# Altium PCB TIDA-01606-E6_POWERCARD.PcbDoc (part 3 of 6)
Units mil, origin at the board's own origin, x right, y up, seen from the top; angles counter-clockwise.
Board outline 13779.53 x 7874.02 mil, 4 copper layers (Top Layer, Gnd Layer, Pwr Layer, Bottom Layer), stack 94.4 mil thick; 550 components, 292 nets, 1594 pads, 572 vias.
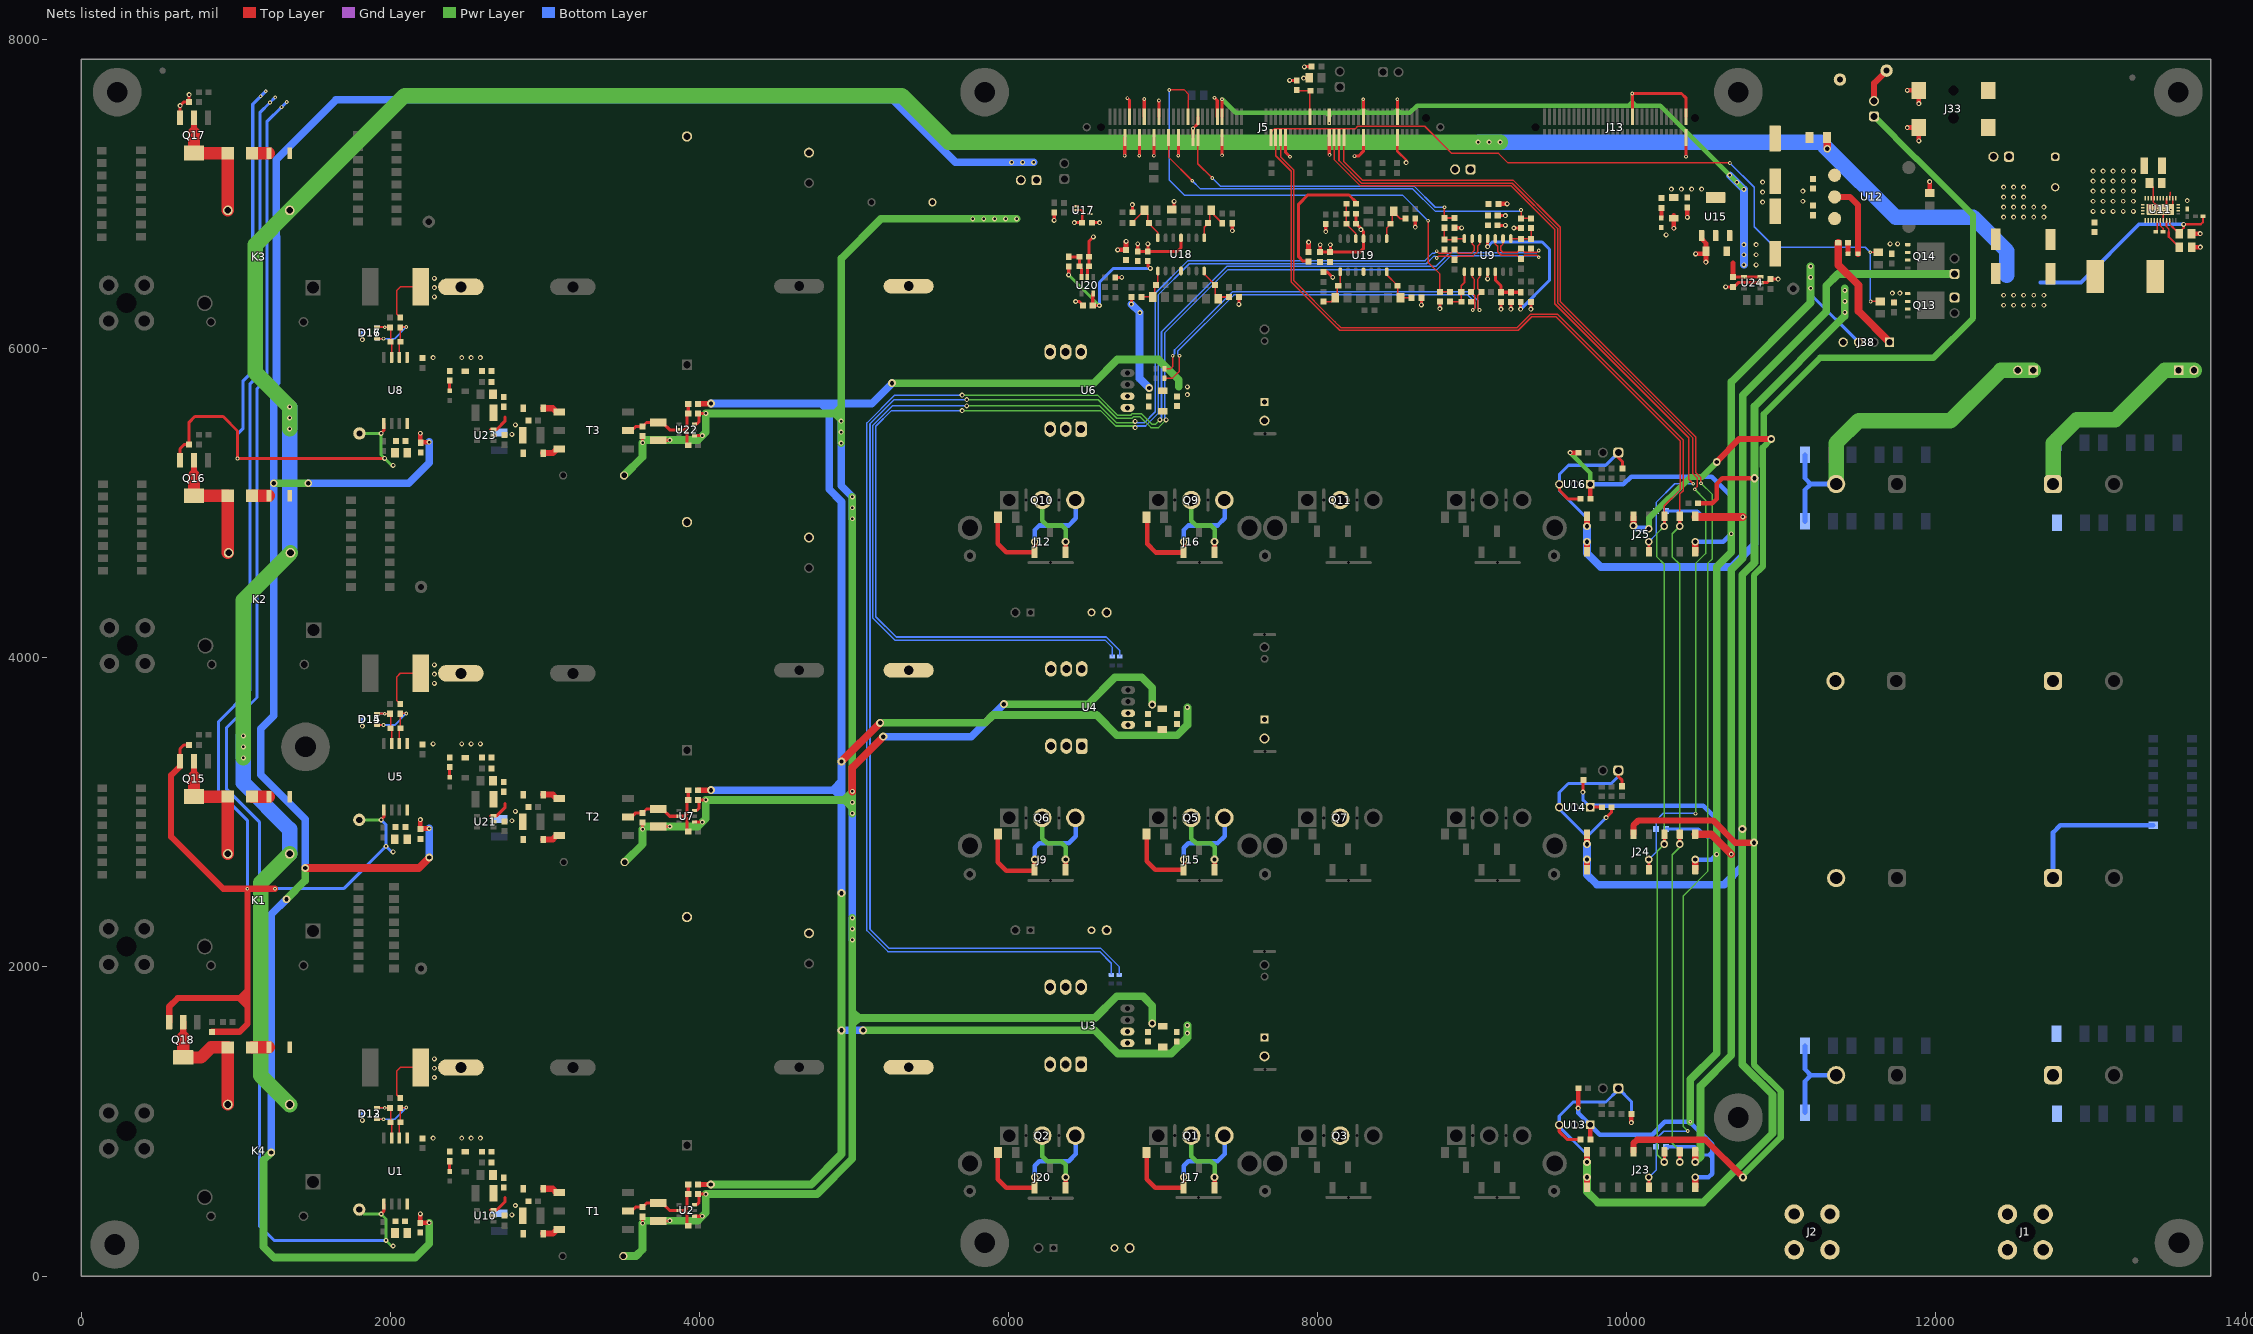
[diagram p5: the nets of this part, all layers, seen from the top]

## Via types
v1: diameter 32, hole 16, Top Layer to Bottom Layer, 336 vias
v2: diameter 24, hole 12, Top Layer to Bottom Layer, 140 vias
v3: diameter 50, hole 28, Top Layer to Bottom Layer, tented both sides, 65 vias
v4: diameter 52, hole 28, Top Layer to Bottom Layer, 14 vias
v5: diameter 19.68, hole 7.87, Top Layer to Bottom Layer, 10 vias
v6: diameter 50, hole 28, Top Layer to Bottom Layer, 7 vias

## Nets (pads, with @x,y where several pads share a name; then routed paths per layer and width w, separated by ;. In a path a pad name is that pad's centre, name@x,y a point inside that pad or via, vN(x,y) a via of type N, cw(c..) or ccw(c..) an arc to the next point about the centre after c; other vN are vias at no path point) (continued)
3.3V: C44.1 C49.1 C53.2 C90.2 C91.2 C92.2 J23.16 J24.16 J25.16 J38.3 L7.1 L8.1 L13.1 L17.1 L21.1 L23.1 R8.2 R11.2 R32.2 R35.2 R55.2 R64.2 R91.2 R208.2 U13.1 U14.1 U15.2 U15.4 U16.1 U17.1 U17.4 U17.5 | length 29376.6
  Top Layer w15: C53.2@6528.29,6826.56 C53.2@6539.3,6815.55
  Top Layer w20: C53.2@6539.3,6815.55 v1(6589.8,6815.55) ; v1@6760.41,6694 v1(6760.87,6694.46) ; v1(7909,7750) 7912,7753 R35.2@7945.33,7753 R35.2@7951.87,7753 ; v1@7941,6689 v1(7941.46,6689.46) ; v1(9716,3131) 9716,3204.5 R64.2@9720,3208.5 ; U14.1@9763.54,3034 C91.2@9839.5,3034
  Top Layer w30: v1(2195,402.98) 2195,346 v1(2251.98,346) ; v1(2195,2952.98) 2195,2896 v1(2251.98,2896) ; v1(2195,5452.98) 2195,5396 v1(2251.98,5396) ; v1(6705.87,6639.46) 6760.41,6639.46 v1@6760.41,6694 ; L23.1@7941,6634.46 v1@7941,6689 ; L17.1@9169.5,6937 v1(9226,6937) ; v1(9633.33,5327.33) R91.2@9687.01,5327.33 ; v1(9686,1087) 9687.01,1088.01 R55.2@9687.01,1215.2 ; U13.1@9763.54,977.94 9764.5,976.98 C90.2@9764.5,884 ; U16.1@9764.61,5122.01 9764.6,5029.39 C92.2@9764.99,5029
  Top Layer w40: J23.16@10442.93,574.56 v3(10442.93,638.93) ; J24.16@10442.93,2630.62 v3(10442.93,2694.99) ; J25.16@10442.93,4686.69 v3(10442.93,4751.06)
  Top Layer w50: v6(1450,2640) 2184,2640 v6(2251.98,2707.98)
  Pwr Layer w30: v1(9633.33,5327.33) 9764.6,5196.06 U16.1@9764.61,5122.01
  Pwr Layer w50: v6(1230,800) 1180,750 1180,190 1250,120 2162.14,120 2251.98,209.85 v1(2251.98,346) ; v6(1247,5130) v6(1470,5130) ; v6(1329,2439) 1450,2560 v6(1450,2640) ; v2(10411,999) 10411,1272 10582,1443 10582,2708 v1(10582,2729) 10582,4589 10676,4683 v1(10676,4803) 10676,5784 11189,6297 v1(11189,6391) v1(11189,6462) v1(11189,6533)
  Bottom Layer w20: v1(9716,3131) 9716,3081.54 U14.1@9763.54,3034 ; R32.2@10252.79,837.06 10441.94,837.06 10494,785 10530,785 ; R8.2@10252.79,2893.12 10464.88,2893.12 10516,2842 10582,2842 ; R11.2@10252.79,4949.18 10458.94,4949.18 10503.13,4905 10676,4905 ; 10552,763 10530,785 ; 10552,785 10530,785 ; 10552,807 10530,785 ; v1(11189,6391) 11189,6353.17 J38.3@11500,6042.18
  Bottom Layer w30: v1(9686,1087) 9686,1055.47 9826.47,915 10163.87,915 10246.87,998 10406,998 10552,852 10552,807 10552,785 10552,763 10552,662 10528.93,638.93 v3(10442.93,638.93) ; U14.1@9763.54,3034 9772.53,3043 10495,3043 10582,2956 10582,2842 v1(10582,2729) 10547.99,2694.99 v3(10442.93,2694.99) ; U16.1@9764.61,5122.01 9978.01,5122.01 10028,5172 10549,5172 10676,5045 10676,4905 v1(10676,4803) 10624.05,4751.06 v3(10442.93,4751.06)
  Bottom Layer w50: v6(1230,800) 1230,2340 v6(1329,2439) ; v6(1450,2640) 1450,2955 1162,3243 1162,3541.4 1247,3626.4 v6(1247,5130) 1247,5763.31 1264.37,5780.68 1264.37,6725.17 1263,6726.55 1263,7223 1650,7610 5253,7610 5657,7206 v1(6021,7206) v1(6092,7206) v1(6163,7206) ; v6(1470,5130) 2120,5130 2251.98,5261.98 v1(2251.98,5396) ; v6(2251.98,2707.98) v1(2251.98,2896)
  other v1: 10289,7032 10354,7032 10419,7032 10484,7032
3.3V_U9: C36.2 C37.1 L17.2 R128.1 U9.4 | length 994.8
  Top Layer w20: U9.4@9099.7,6712.46 9099.7,6660.3 v1(9100,6660) ; v1(9313.24,6256.25) 9313.74,6256.75 R128.1@9313.74,6302.25
  Bottom Layer w20: v1(9100,6660) 9130,6690 9453,6690 9500,6643 9500,6443.01 v1(9313.24,6256.25)
3.3V_U18: C47.2 C56.1 C135.2 L21.2 R142.1 U18.4 U20.5 | length 1025.8
  Top Layer w20: v1@6390,6477.67 R142.1@6390,6532.01 ; U20.5@6547.4,6355.87 6545.5,6353.96 C135.2@6545.5,6280 v1@6589,6280 ; C56.1@6901.54,6566.68 6901.54,6536.46 v1(6918,6520)
  Pwr Layer w20: v1(6389.5,6477.18) 6587.18,6279.5 v1(6588.5,6279.5)
  Bottom Layer w20: v1(6588.5,6279.5) 6588.5,6429.37 6679.13,6520 v1(6918,6520)
3.3V_U19: C57.2 C58.1 L23.2 R139.1 U19.4 | length 841.5
  Top Layer w20: L23.2@7941,6567.54 7903.46,6567.54 7877,6594 7877,6935 7936,6994 8203,6994 8249.2,6947.8 R139.1@8249.2,6938
5V: C43.1 C62.1 C66.1 C117.2 J5.48 J5.84 J5.98 J5.112 J13.158 J13.180 J38.1 L9.1 L10.1 L14.1 R53.2 R63.2 R159.2 R207.2 U12.3 U15.3 U24.3 U24.4 | length 22284.4
  Top Layer w20: v2(7382,7614) 7382.4,7613.6 J5.48@7382.4,7500.07 ; v2(8075.31,7460) J5.84@8075.31,7500.07 ; v2(8295.39,7614) 8295.78,7613.6 J5.98@8295.78,7500.07 ; v2(8515.86,7614) 8516.26,7613.6 J5.112@8516.26,7500.07 ; v2(10035.54,7651.34) 10354.66,7651.34 10382.4,7623.6 J13.180@10382.4,7500.07 ; J13.158@10035.94,7500.07 v2@10035.94,7650.94 ; C117.2@10687.61,6463.54 10688.51,6464.44 U24.3@10865.74,6464.44
  Top Layer w30: R53.2@3990.5,592 R53.2@3991.5,593 ; R63.2@3991.5,3143 R63.2@3992.5,3144 ; R159.2@3991.5,5643 R159.2@3993.5,5645 ; C117.2@10687.61,6463.54 10687.61,6554.61
  Top Layer w35: R53.2@3991.5,593 v4(4074,593) ; R63.2@3992.5,3144 v4(4075,3144) ; R159.2@3993.5,5645 v4(4076,5645)
  Top Layer w50: v4(4920,3330) v4(5170,3580) ; R207.2@11368.5,6685 11368.5,6541.5 11500,6410 11500,6242.18 J38.1@11700,6042.18
  Pwr Layer w20: 8045.09,7531 8050.09,7526 8075,7501.09 ; 8073,7526 8074.91,7527.91 ; 8075,7529.09 8075,7526 8075,7501.09 ; v2(8075.31,7460) 8075.31,7500.78 8075,7501.09 ; 8104.83,7526 8107,7526 ; 8104.91,7531 8099.91,7526 8075,7501.09 ; 8273,7526 8273,7531.61 8295.39,7554 ; v2(8295.39,7614) 8295.39,7554 ; 8295.78,7526 8295.39,7526.4 8295.39,7554 ; 8335,7526 8323.39,7526 8295.39,7554 ; 8488,7526 8515.86,7553.86 ; 8515,7526 8515.86,7526.86 8515.86,7553.86 ; v2(8515.86,7614) 8515.86,7553.86 ; 8550,7526 8543.72,7526 8515.86,7553.86 ; 10007.68,7574.14 10035.54,7602 ; 10035.54,7573.4 10035.54,7602 ; v2(10035.54,7651.34) 10035.54,7602 ; 10063.4,7574.14 10035.54,7602
  Pwr Layer w30: v2(7382,7614) 7470,7526 8050.09,7526 8073,7526 8075,7526 8099.91,7526 8104.83,7526 ; 8107,7526 8273,7526 8295.78,7526 8323.39,7526 ; 8335,7526 8488,7526 8515,7526 8543.72,7526 ; 8550,7526 8597,7526 8644,7573 10216,7573 v1(10666.08,7122.92) v1(10712.04,7076.96) v1(10758,7031)
  Pwr Layer w50: v4(4074,593) 4723,593 4920,790 v4(4920,1590) v3(4920,2478) ; v4(5060,1590) 6557.5,1590 6707.5,1440 7053.98,1440 7158,1544.02 v1(7158,1572.87) v1(7158,1622.87) ; v4(5170,3580) 5850,3580 5900,3630 6570,3630 6700,3500 7092,3500 7158,3566 v1(7158,3678.94) ; v4(5247,5777) 6550.92,5777 6703.92,5930 6970,5930 7101,5799 7101,5754
  Bottom Layer w50: v4(4075,3144) 4874,3144 4920,3098 ; v4(4076,5645) 4790,5645 ; 4840,5600 4845,5600 4890,5645 ; 4870,3150 4920,3200 ; v4(4920,1590) v4(5060,1590) ; v3(4920,2478) 4920,3098 ; v4(5247,5777) 5115,5645 4890,5645 ; v1(10666.08,7122.92) v1(10712.04,7076.96) ; v1@10721.96,7067.04 v1(10758,7031) v1(10758,6673) v1(10758,6608) v1(10758,6543) ; 4790,5645 4890,5645 ; 4790,5645 4840,5595 4840,5090 4920,5010 v4(4920,3330) 4920,3200 ; 4920,3098 4920,3200
  other v1: 7158,5703 7158,5753 10837,6543 10837,6608 10837,6673
5V_1: C28.1 D12.3 D28.1 R155.2 R156.2 U1.1 | length 43.8
  Bottom Layer w20: v1(1820.76,1008.24) D12.3@1820.76,1052
  other v1: 2278,893 2463,893 2523,893 2583,893
5V_2: C35.1 D14.3 D29.1 R157.2 R158.2 U5.1 | length 43.8
  Bottom Layer w20: v1(1820.76,3558.24) D14.3@1820.76,3602
  other v1: 2278,3443 2463,3443 2523,3443 2583,3443
5V_3: C18.1 D16.3 D33.1 R161.2 R162.2 U8.1 | length 43.8
  Bottom Layer w20: v1(1820.76,6058.24) D16.3@1820.76,6102
  other v1: 2278,5943 2463,5943 2523,5943 2583,5943
24V: J33.1 J33.1A J34.2 J39.2 TP2.1 | length 229.6
  Top Layer w40: J39.2@11599.76,7603.05 11599.76,7717.76 TP2.1@11681,7799
+6V_VDC_1: C93.1 C94.1 C97.2 C99.1 D9.1 D24.1 U10.2
  other v1: 2787,396 2810,457
+6V_VDC_2: C95.1 C96.1 C98.2 C100.1 D11.1 D25.1 U21.2
  other v1: 2787,2946 2810,3007
+6V_VDC_3: C110.1 C111.1 C112.2 C113.1 D30.1 D31.1 U23.2
  other v1: 2787,5446 2810,5507
+12V: C48.1 C119.1 C125.1 C126.1 D1.2 D2.2 D4.2 D5.2 J23.15 J24.15 J25.15 J26.1 J28.1 K1.3 K2.3 K3.3 K4.3 L16.2 L19.1 R54.2 U11.9 | length 27835.7
  Top Layer w10: U11.9@13511.68,6829.3 13511.68,6806.32 13531.68,6786.32
  Top Layer w15: 13531.68,6786.32 C125.1@13574,6744 13574,6754 13603,6783 v1(13603,6805) 13714,6805 13727.62,6818.62 R54.2@13727.62,6857
  Top Layer w40: v3(10442.93,738.93) J23.15@10442.93,803.3
  Top Layer w50: J24.15@10442.93,2859.36 10545.64,2859.36 v1(10676,2730) ; J25.15@10443.75,4911.87 v1(10751.13,4911.87) ; v3(11296.79,7293.79) L19.1@11296.79,7367
  Pwr Layer w50: v3(10442.93,738.93) 10477,773 10477,1229.72 10676,1428.72 v1(10676,2730) 10676,4570 10751.13,4645.13 v1(10751.13,4911.87) 10751.13,5699.13 11290.5,6238.5 11290.5,6406.5 11367,6483 J28.1@12121.99,6483
  Pwr Layer w100: v1(1050,3353) v1(1050,3424) v1(1050,3495) 1050,4374 K2.3@1355,4679 ; K4.3@1350,1110 1162,1298 1162,2544 K1.3@1350,2732 ; v1(1350,5481) v1(1350,5552) v1(1350,5623) 1127,5846 1127,6672 K3.3@1350,6895 2093,7638 5310,7638 5612,7336 v1(9039,7336) v1(9110,7336) v1(9181,7336)
  Bottom Layer w15: v1(13603,6805) v1@13604,6806
  Bottom Layer w25: 12677.07,6428.68 12938.68,6428.68 13315,6805 v1(13603,6805)
  Bottom Layer w100: v1(1050,3495) v1(1050,3424) v1(1050,3353) 1050,3190.4 1350,2890.4 K1.3@1350,2732 ; K2.3@1350,4684 v1(1350,5481) v1(1350,5552) v1(1350,5623) ; v1(9039,7336) v1(9110,7336) v1(9181,7336) 11254.57,7336 v3(11296.79,7293.79) 11739.57,6851 12240,6851 12459,6632 12459,6476
  other v1: 12438,6281 12503,6281 12568,6281 12633,6281 12698,6281 12438,6346 12503,6346 12568,6346 12633,6346 12698,6346
+24V: C89.1 C123.1 C124.1 J34.1 U11.18 U11.20 U11.21 U11.22 | length 40.4
  Top Layer w10: U11.18@13511.68,6973 13511.68,6990.05 13515,6993.37 13515,7012
+24V_Gate_Boards: J23.7 J24.7 J25.7 J39.1 | length 11421
  Top Layer w40: J23.7@10042.93,803.3 10042.93,859.36 10066.36,882.79 10508.6,882.79 v4(10752.09,639.3) ; J24.7@10042.93,2859.36 10043.24,2859.68 10043.24,2915.95 10075.09,2947.8 10558.49,2947.8 10702.29,2804 v4(10823,2804) ; v3(10042.93,4854) J25.7@10042.93,4915.43 ; v3@10581.5,5269.36 10728.15,5416.02 v3(10935.52,5416.02)
  Pwr Layer w40: v3(10142.93,4835.7) 10144.84,4837.61 10144.84,4905.03 10409.69,5169.87 10486.22,5169.87 10581.5,5265.15 v3@10581.5,5269.36 ; v4(10752.09,639.3) 10754.39,641.59 10754.39,654.99 10996.5,897.11 10996.5,1195.27 10823,1368.78 v4(10823,2804) 10823,4533.13 10880.87,4591 10880.87,5237.34 10879.87,5238.34 10879.87,5360.38 v3(10935.52,5416.02) 10886,5416.02 10886,5577.34 11250.66,5942 11984.45,5942 12241,6198.55 12241,6864.45 11876.11,7229.34 11873.47,7229.34 J39.1@11599.76,7503.05
  Bottom Layer w40: v3(10042.93,4854) 10045.64,4854 10062.02,4837.61 10141.02,4837.61 v3(10142.93,4835.7)
  other v3: 10581.5,5267.26
DC+: C1.1 C2.1 C3.1 C4.1 C5.1 C73.1 C74.1 C120.1 C121.1 C122.1 J1.1 J15.4 J16.4 J17.4 J36.1 J36.2 Q1.2 Q5.2 Q9.2 R1.2 R2.2 R132.1 R180.2 R181.2 | length 3699.9
  Top Layer w30: J17.4@7333.48,572 v3(7333.48,638.93) ; J15.4@7333.48,2628.06 v3(7333.48,2694.99) ; J16.4@7333.48,4684.13 v3(7333.48,4751.06)
  Pwr Layer w30: Q1.2@7183.48,908.93 7183.48,774.24 7213.78,743.94 7309.84,743.94 7333.48,720.3 v3(7333.48,638.93) ; Q5.2@7183.48,2964.99 7183.48,2830.3 7213.78,2800 7309.84,2800 7333.48,2776.36 v3(7333.48,2694.99) ; Q9.2@7183.48,5021.06 7183.48,4886.36 7213.78,4856.06 7309.84,4856.06 7333.48,4832.43 v3(7333.48,4751.06)
  Pwr Layer w100: C4.1@12757.85,5124.48 12757.85,5387.85 12910,5540 13160,5540 13480,5860 J36.1@13570,5860 J36.2@13670,5860
  Bottom Layer w30: C74.1@12757.85,2575 12757.85,2870 12805.3,2917.45 R132.1@13406,2917.45
DC-: C6.2 C7.2 C11.2 C12.2 C13.2 C75.2 C76.2 C127.2 C128.2 C129.2 J2.1 J9.2 J12.2 J20.2 J35.1 J35.2 Q2.3 Q6.3 Q10.3 R14.1 R15.1 R190.1 R191.1 R192.1 R193.1 R194.1 | length 5964.3
  Top Layer w30: R192.1@5931.57,800 5931.57,627.09 5986.66,572 J20.2@6169.7,572 v3(6169.7,638.93) ; R193.1@5931.57,2851.07 5931.57,2678.16 5986.66,2623.07 J9.2@6169.7,2623.07 ; R194.1@5931.57,4912.13 5931.57,4739.21 5986.66,4684.13 J12.2@6169.7,4684.13 v3(6169.7,4751.06) ; J9.2@6169.7,2628.06 v3(6169.7,2694.99)
  Pwr Layer w100: C7.2@11355,5124.48 11355,5389 11500,5534 12094,5534 12420,5860 J35.2@12530,5860 J35.1@12630,5860
  Bottom Layer w30: v3(6169.7,638.93) 6169.7,714.98 6198.66,743.94 6388.66,743.94 6434.7,789.98 Q2.3@6434.7,908.93 ; v3(6169.7,2694.99) 6169.7,2771.04 6198.66,2800 6388.66,2800 6434.7,2846.04 Q6.3@6434.7,2964.99 ; v3(6169.7,4751.06) 6169.7,4827.1 6198.66,4856.06 6388.66,4856.06 6434.7,4902.1 Q10.3@6434.7,5021.06 ; R191.1@11153.3,1058.07 11153.3,1261.78 11191.52,1300 ; R190.1@11153.3,1489.97 11153.3,1338.22 11191.52,1300 ; R14.1@11153.3,4882.55 11153.3,5086.26 11191.52,5124.48 ; R15.1@11153.3,5314.45 11153.3,5162.7 11191.52,5124.48 ; C6.2@11355,1300 11191.52,1300 ; C7.2@11355,5124.48 11191.52,5124.48
FAN_CNTL: J5.59 R59.1 R66.1 | length 4846.7
  Top Layer w10: J5.59@7697.36,7366.21 7697.36,7400 7721.48,7424.13 8245.79,7424.13 8260.12,7438.45 8692.94,7438.45 8868.29,7263.1 9170.87,7263.1 9231.97,7202 v2(10667,7202) ; v2(11575.29,6624.22) 11575.75,6623.76 R66.1@11626.54,6623.76 ; v2(11578,6306) R59.1@11640.79,6306
  Bottom Layer w10: v2(10667,7202) 10825,7044 10825,6789 10957,6657 11542.51,6657 v2(11575.29,6624.22) v2@11575.29,6306
FLT_A: J5.89 J23.10 R32.1 | length 8636.3
  Top Layer w10: J5.89@8169.8,7366.21 8169.8,7211.19 8291.99,7089 9266.92,7089 9570.04,6785.88 9570.04,6304.94 10445.75,5429.23 10445.75,5198.97 10480,5164.72 v2(10480,5130)
  Top Layer w20: J23.10@10142.93,574.56 v3(10142.93,638.93)
  Pwr Layer w10: v2(10395,938.87) 10365,968.87 10365,2460 10523,2618 10523,4610 10554,4641 10554,5056 v2(10480,5130)
  Bottom Layer w10: v3(10142.93,638.93) 10189.79,685.8 10189.79,888.8 10238.87,937.87 10394,937.87 v2(10395,938.87)
FLT_B: J5.87 J24.10 R8.1 | length 6577.9
  Top Layer w10: J5.87@8138.3,7366.21 8138.3,7217.41 8284.58,7071.13 9259.52,7071.13 9552.17,6778.48 9552.17,6297.53 10427.87,5421.82 10427.87,5191.57 10454.87,5164.57 10454.87,5108.66 10440,5093.79 v2(10440,5090)
  Top Layer w20: J24.10@10142.93,2630.62 v3(10142.93,2694.99)
  Pwr Layer w10: v2(10440,5090) 10510,5020 10510,4675 10445,4610 v2(10445,2992)
  Bottom Layer w10: v3(10142.93,2694.99) 10189.79,2741.86 10189.79,2947.8 10235.94,2993.94 v2@10445,2993.94
FLT_C: J5.85 J25.10 R11.1 | length 4402.1
  Top Layer w10: J5.85@8106.81,7366.21 8106.81,7223.63 8277.18,7053.25 9252.11,7053.25 9534.29,6771.07 9534.29,6290.13 10400.99,5423.43 10400.99,5155.01 v2(10430,5126)
  Top Layer w20: J25.10@10142.93,4686.69 v3(10142.93,4751.06)
  Bottom Layer w10: v3(10142.93,4751.06) 10189.79,4797.92 10189.79,5005.8 10310,5126 v2(10430,5126)
GND: C14.1 C15.2 C16.1 C17.1 C20.2 C21.1 C22.2 C23.2 C24.2 C25.2 C26.1 C27.1 C29.1 C30.2 C31.2 C32.2 C33.1 C34.1 C36.1 C37.2 C38.2 C39.1 C40.1 C41.1 C42.1 C43.2 C44.2 C45.1 C46.1 C47.1 C48.2 C49.2 C50.1 C51.1 C52.1 C53.1 C54.1 C55.1 C56.2 C57.1 C58.2 C59.1 C60.1 C61.2 C62.2 C63.1 C64.2 C65.2 C66.2 C67.2 C68.2 C69.1 C70.1 C71.1 C72.1 C89.2 C90.1 C91.1 C92.1 C107.1 C108.1 C109.1 C117.1 C118.2 C119.2 C123.2 C124.2 C125.2 C126.2 C130.1 C131.1 C132.1 C134.1 C135.1 D18.1 D19.1 GND_1.1 GND_2.1 GND_3.1 J5.7 J5.10 J5.13 J5.16 J5.19 J5.22 J5.29 J5.35 J5.38 J5.46 J5.47 J5.65 J5.83 J5.97 J5.111 J8.1 J8.2 J13.179 J23.1 J23.2 J24.1 J24.2 J25.1 J25.2 J27.1 J29.1 J30.1 J33.2 J33.3 J37.1 J37.2 J38.4 Q13.1 Q13.2 Q13.3 Q14.1 Q14.2 Q14.3 Q15.3 Q16.3 Q17.3 Q18.3 R38.1 R57.1 R60.1 R72.1 R76.1 R130.2 R141.2 R144.2 R167.1 R201.1 R202.1 R203.1 R204.1 R206.1 TP3.1 U1.5 U2.4 U2.6 U3.13 U4.13 U5.5 U6.13 U7.4 U7.6 U8.5 U9.11 U11.7 U11.13 U11.14 U11.15 U11.16 U11.17 U11.19 U11.23 U11.24 U11.25 U11.26 U11.27 U11.28 U11.29 U11.30 U11.31@13452.63,6901.15 U12.2 U13.3 U14.3 U15.1 U16.3 U17.2 U18.11 U19.11 U20.2 U22.4 U22.6 U24.2 | length 65485.2
  Top Layer w10: C124.2@13382,7072 13404.84,7049.15 13404.84,6948.93 13417.39,6936.39 U11.31@13452.63,6901.15 ; U11.7@13472.31,6829.3 13472.31,6881.46 U11.31@13452.63,6901.15 ; U11.31@13492,6926.74 U11.19@13492,6973 ; U11.17@13531.37,6977.01 U11.17@13531.37,6973 13531.37,6912.37 13520.15,6901.15 v5(13519.95,6901.15) v5(13475.07,6901.15) U11.31@13452.63,6901.15
  Top Layer w15: U17.2@6439.71,6897 6469.35,6897 6476.8,6889.55 6476.8,6816.05 C53.1@6476.31,6815.55 ; J5.111@8516.26,7366.21 8516.26,7276.74 8573,7220 v1(8573,7204)
  Top Layer w20: Q15.3@640.45,3331.17 640.45,3411.45 665,3436 R201.1@699.5,3436 ; Q16.3@640.45,5277.17 640.45,5352.45 668,5380 R204.1@699.5,5380 699.5,5524.5 736,5561 919,5561 1012,5468 v2(1012,5290) v1(1964,5290) ; Q17.3@640.45,7494.17 v1(640.45,7572.45) 664,7596 R202.1@699.5,7596 v1(699.5,7643.5) ; v1(1941,402) 1959.45,420.45 U1.5@1959.45,465.43 ; v1(1941,2952) 1959.45,2970.45 U5.5@1959.45,3015.43 ; v1(1941,5452) 1959.45,5470.45 U8.5@1959.45,5515.43 ; v1(3633,342) C33.1@3633,384 ; v1(3633,2892) C34.1@3633,2934 ; v1(3633,5392) C109.1@3633,5434 ; C16.1@3734,357.91 3808.91,357.91 v1(3810,359) ; C17.1@3734,2907.91 3808.91,2907.91 v1(3810,2909) ; C107.1@3734,5407.91 3808.91,5407.91 v1(3810,5409) ; U2.4@3973.14,387.6 v1(4019.4,387.6) ; U2.6@3973.14,462.4 3982.4,462.4 3999,479 3999,523.5 C26.1@3991.5,531 v1(4042,531) ; U7.4@3973.14,2937.6 v1(4019.4,2937.6) ; U7.6@3973.14,3012.4 3982.4,3012.4 3999,3029 3999,3073.5 C27.1@3991.5,3081 v1(4042,3081) ; U22.4@3973.14,5437.6 v1(4019.4,5437.6) ; U22.6@3973.14,5512.4 3982.4,5512.4 3999,5529 3999,5573.5 C108.1@3991.5,5581 v1(4042,5581) ; v1(6296,6830.55) C52.1@6296,6881.05 ; v1(6425.8,6815.55) C53.1@6476.31,6815.55 ; v1@6434.7,6306 6456.5,6306 C135.1@6482.5,6280 ; U20.2@6510,6464.13 6510,6521.5 C71.1@6521.5,6533 R144.2@6521.5,6594.33 6521.5,6695.5 v1(6550,6724) ; C72.1@6691.5,6461.5 v1@6733.51,6461.5 ; v2(6751.51,7248.93) 6752.48,7247.96 J5.7@6752.48,7366.21 ; v2(6768.94,7621) 6783.97,7605.97 J5.10@6783.97,7500.07 ; v1(6795.61,6288.5) 6796.11,6289 C51.1@6796.11,6334.5 ; v1(6801.5,6931.88) C134.1@6801.5,6883.38 C134.1@6802,6883.88 ; v1(6836.54,6677.67) 6836.54,6629.17 C47.1@6837.05,6629.67 C56.2@6901.54,6629.67 ; v2(6846,7248.93) 6846.96,7247.96 J5.13@6846.96,7366.21 ; J5.16@6878.46,7500.07 v2(6878.46,7615.54) ; C56.2@6901.54,6629.17 C56.2@6901.54,6629.67 ; v1(6901.54,6677.67) C56.2@6901.54,6629.67 ; v2(6940.49,7248.93) 6941.45,7247.96 J5.19@6941.45,7366.21 ; J5.22@6972.95,7500.07 v2(6972.98,7606) ; C22.2@6985.21,1616.66 C22.2@6998.08,1616.66 ; C24.2@6985.21,3672.72 C24.2@6998.08,3672.72 ; C31.2@6985.21,5728.79 C31.2@6998.08,5728.79 ; R206.1@7056.41,6901 7071.37,6915.95 v1(7071.37,6953.74) ; v2(7097.97,7248.93) 7098.93,7247.96 J5.29@7098.93,7366.21 ; U18.11@7116.24,6717.46 7117.41,6716.29 7117.41,6654 7093.08,6629.67 C56.2@6901.54,6629.67 ; J5.35@7193.42,7366.21 7193.42,7424.42 v2(7194,7425) 7224.92,7455.92 J5.38@7224.92,7500.07 ; v2(7333,7623.87) 7350.9,7605.97 J5.46@7350.9,7500.07 ; v2(7382.4,7251) J5.47@7382.4,7366.21 ; v1(7448,6763) C55.1@7448,6811.5 ; v1(7491,6287) 7491.11,6287.11 C54.1@7491.11,6334.5 ; J5.65@7791.85,7366.21 7791.85,7271.15 v2(7821,7242) ; v1(7819.33,7736) 7819.83,7735.5 C46.1@7865.63,7735.5 ; v1(7914,7823) 7916,7825 R38.1@7960.83,7825 ; v1(8017.13,6672.67) 8017.13,6624.17 8017.63,6624.67 C58.2@8082.13,6624.67 ; C59.1@8038.3,6495.5 8063.5,6495.5 v1(8098,6461) ; v1(8052.7,6758) C70.1@8052.7,6806.5 ; J5.83@8075.31,7366.21 8075.31,7254.31 8075.62,7254 v2(8078,7254) ; C58.2@8082.13,6624.17 C58.2@8082.13,6624.67 ; v1(8082.13,6672.67) C58.2@8082.13,6624.67 ; v2(8238,7246) 8264.65,7246 8295.78,7277.13 J5.97@8295.78,7366.21 ; R141.2@8249.2,6873 C69.1@8249.2,6808 8285,6772.2 8283.8,6771 8296.83,6757.97 U19.11@8296.83,6712.46 8298,6711.29 8298,6649 8273.67,6624.67 C58.2@8082.13,6624.67 ; v1(8631.7,6786.2) C63.1@8631.7,6841.5 ; v1(8671.2,6284.01) 8671.7,6284.5 C60.1@8671.7,6329.5 C60.1@8671.7,6330.01 ; v1(8790.5,6258.77) 8791,6259.27 C45.1@8791,6304.77 ; C40.1@8885.7,6782.5 8931.2,6782.5 v1(8931.7,6782.01) ; v1(9099.2,6451.89) 9099.7,6452.39 U9.11@9099.7,6497.89 ; C37.2@9164.2,6798.17 v1(9214.17,6798.17) ; C36.1@9165.2,6861.17 v1(9215.17,6861.17) ; v1(9186.4,6256.25) 9186.9,6256.75 C132.1@9186.9,6302.25 ; v1(9249.96,6256.25) 9250.46,6256.75 R130.2@9250.46,6302.25 ; v1(9270,6781) 9270.5,6780.5 C41.1@9316,6780.5 ; v1(9380.21,6256.25) 9380.7,6256.75 C131.1@9380.7,6302.25 ; U13.3@9563.54,977.94 9563.53,934.46 9614,884 C90.1@9701.5,884 ; U16.3@9564.61,5122.01 9564.6,5083.39 9619,5029 C92.1@9702,5029 ; v1(9866,2966) 9902.5,3002.5 C91.1@9902.5,3034 ; J29.1@9945,3271.27 9945,3232.83 9970,3207.83 C42.1@9970,3169.39 ; J30.1@9945,5327.33 9945,5296 9972,5269 C50.1@9972,5224.99 ; J13.179@10382.4,7366.21 10382.4,7242.4 v2(10383.4,7242.4) ; v1(10639.46,6400.54) 10694.54,6400.54 10721.04,6427.04 10907.11,6427.04 C118.2@10930.61,6450.54 v1(10978.75,6450.54) ; R60.1@11729.25,6307.25 R60.1@11735.25,6307.25 ; v1@11959.7,7081.3 v1(11960,7081)
  Top Layer w30: v1(10029.99,993.36) C39.1@10029.99,1049 ; v1@10304,6779.3 C49.2@10304,6844.07 ; C49.2@10304,6863.3 C49.2@10305,6863.3 ; C44.2@10391,6914.5 10391,6849.73 v1(10392,6849.73) ; v1(10445,6613) 10445,6614 10509.77,6614 C43.2@10512.77,6611 ; R167.1@10461.5,5000 10554,5000 10581.5,5027.5 10581.5,5124.5 10619,5162 v4(10827,5162) ; U15.1@10484.15,6732.16 10484.15,6710.85 10512.77,6682.23 C43.2@10512.77,6611 ; v1(10512,6560) 10512.77,6560.77 C43.2@10512.77,6611 ; v1(11814.7,7431) J33.3@11889,7431 11890,7430 v1(11890,7345) ; v1(11814.7,7671.16) J33.2@11889,7671.16 11890,7670.16 v1(11890,7585.16) ; R72.1@11959.7,7007 v1@11959.7,7081.3 ; C125.2@13654,6744 v1(13710,6744) ; C38.2@13655,6657 v1(13711,6657)
  Top Layer w40: Q18.3@570.45,1643.17 570.45,1744.45 625,1799 1027,1799 ; Q15.3@640.45,3331.17 640.45,3298.45 583,3241 583,2843 920,2506 v2(1076,2506) ; R203.1@848,1580.5 1025.5,1580.5 1076,1631 1076,1747 ; v2(1255,2506) v2(1076,2506) ; J23.2@9742.93,574.56 v3(9742.93,638.93) ; v3(9742.93,738.93) J23.1@9742.93,803.3 ; J24.2@9742.93,2630.62 v3(9742.93,2694.99) ; v3(9742.93,2794.99) J24.1@9742.93,2859.36 ; J25.2@9742.93,4686.69 v3(9742.93,4751.06) ; v3(9742.93,4851.06) J25.1@9742.93,4915.43 ; U12.2@11344.74,6982 11443,6982 11496.48,6928.52 D18.1@11496.48,6614 ; 1027,1799 1074,1846 1076,1846 ; 1027,1799 1074,1799 1076,1801 ; 1027,1799 1027,1796 1076,1747 ; 1076,1747 1076,1801 ; 1076,1801 1076,1846 ; 1076,1846 v2(1076,2506)
  Top Layer w50: v1(4990,3135.5) 4990,3290 v4(5190,3490)
  Gnd Layer w20: v1(8280,6771) v1@8280,6775
  Pwr Layer w20: GND_1.1@1800,430.55 1828.55,402 v1(1941,402) 1973,370 v1(1973,231) 2009,195 v1(2019,195) ; GND_2.1@1800,2952 v1(1941,2952) ; GND_3.1@1800.79,5452 v1(1941,5452) 1941,5313 v1(1964,5290) 2009,5245 v1(2019,5245)
  Pwr Layer w50: C65.2@3508.98,130 3590,130 3633,173 v1(3633,342) 3650,359 v1(3810,359) 3990.8,359 v1(4019.4,387.6) 4042,410.2 v1(4042,531) 4761,531 4990,760 4990,1630 ; C68.2@3512.85,5180 3633,5300.15 v1(3633,5392) 3650,5409 v1(3810,5409) 3990.8,5409 v1(4019.4,5437.6) 4042,5460.2 v1(4042,5581) 4879,5581 ; C67.2@3516.85,2678.91 3633,2795.06 v1(3633,2892) 3650,2909 v1(3810,2909) 3990.8,2909 v1(4019.4,2937.6) 4042,2960.2 v1(4042,3081) 4939,3081 ; v1(4918,5389) v1(4918,5460) v1(4918,5531) ; v1(4990,2318) v1(4990,2247) v1(4990,2176) 4990,1710 ; v1(4990,2993.5) 4990,3030 ; v1@4990,3132 4939,3081 ; v1(4990,5042) v1(4990,4971) v1(4990,4900) v1(4990,3135.5) v1(4990,3064.5) 4990,3030 ; v1@5768,6840 5175,6840 4918,6583 4918,5620 ; v1(5769,6840) v1(5840,6840) v1(5911,6840) v1(5982,6840) v1(6053,6840) ; v4(5970,3700) 6515.53,3700 6689.21,3873.68 6862.32,3873.68 6930,3806 v3(6930,3697.48) ; v3(6930,1635.1) 6930,1750 6870,1810 6700,1810 6560,1670 5030,1670 ; v3(9742.93,738.93) v3(9742.93,638.93) 9742.93,546.07 9812,477 10495.41,477 10943.63,925.21 10943.63,1173.37 10748,1369 v4(10748,2893) 10748,4538 10827,4617 v4(10827,5162) 10827,5628 11411,6212 v1(11411,6235) v1(11411,6306) v1(11411,6377) v1@11411,6391 ; 4879,5581 4918,5542 v1(4918,5531) ; 4879,5581 4918,5620 ; v1(4918,5531) 4918,5620 ; 4939,3081 4990,3030 ; 4990,1630 4990,1710 ; 4990,1630 5030,1670 ; 4990,1710 5030,1670
  Bottom Layer w10: U3.13@6770,1582.5 U3.13@6770,1587.41
  Bottom Layer w20: v2(1012,5290) 1011,5291 1011,5446.13 1046.5,5481.63 1046.5,5789.22 1110.76,5853.47 1110.76,7581.76 v2(1162,7633) v2(1195,7666) ; v2(1076,2506) 1076,2949 890,3135 890,3588 1092.25,3790.25 1092.25,5770.27 1156.5,5834.53 1156.5,7526.5 v2(1223,7593) v2(1256,7626) ; v2(1255,2506) 1254,2507 1699,2507 v1(1973,2781) ; v2(1331,7596) 1330,7596 v2(1297,7563) 1202.25,7468.25 1202.25,5805 1138,5740.75 1138,3744 940,3546 940,3153 1154,2939 1154,326 1249,231 v1(1973,231) ; v1(1941,2952) 1973,2920 v1(1973,2781) ; v1(2019,2745) 2009,2745 v1(1973,2781) ; v3(9742.93,738.93) 9742.93,786.87 9563.53,966.26 9563.53,1036.54 9654,1127 9866,1127 9945,1206 J27.1@9945,1215.2 10029.99,1130.21 v1(10029.99,993.36) ; v3(9742.93,2794.99) 9742.93,2842.93 ; v3@9744,4854 9744,4901.94 9564.6,5081.33 9564.6,5187.54 9623.07,5246.01 9863.68,5246.01 J30.1@9945,5327.33 ; v1(9866,2966) 9742.93,2842.93 ; J29.1@9945,3271.27 9945,3232.94 9899.06,3187 9622,3187 9563.53,3128.54 9563.53,3022.32 9742.93,2842.93
  Bottom Layer w30: v1@13709,6745 v1(13710,6744) ; v1@13710,6658 v1(13711,6657)
  Bottom Layer w50: v1(4918,5531) v1(4918,5460) v1(4918,5389) 4918,5114 v1(4990,5042) v1(4990,4971) v1(4990,4900) ; v1(4990,2176) v1(4990,2247) v1(4990,2318) v1(4990,2993.5) v1(4990,3064.5) v1(4990,3135.5) ; v4(5190,3490) 5760,3490 v4(5970,3700) ; v1(6795.61,6288.5) v1@6848.24,6235.88 ; v1(6850,6234.12) v1@6848.24,6235.88 ; v6(6910,5745.69) 6848.24,5807.45 v1@6848.24,6235.88 ; v3(9742.93,638.93) v3(9742.93,738.93) ; v3(9742.93,2794.99) v3(9742.93,2694.99) 9742.93,2597.07 9808.13,2531.87 10629,2531.87 10748,2650.87 v4(10748,2893) ; v3@9742.93,4852.93 9742.93,4677.07 9832.07,4587.93 10678.93,4587.93 10827,4736 v4(10827,5162)
  other v1: 6434.2,6305.5 11718.25,6360.25 11767.25,6360.25 6733.01,6461 11704,6678 11753,6678 10254,6737 10305,6779.3 12438,6851 12503,6851 12568,6851 12633,6851 12698,6851 13017,6889 13082,6889 13147,6889 13212,6889 13277,6889 12438,6916 12503,6916 12568,6916 12633,6916 12698,6916 10879,6948 11139,6954 13017,6954 13082,6954 13147,6954 13212,6954 13277,6954 13626,6958 12438,6981 12503,6981 12568,6981 10879,7013 11139,7019 13017,7019 13082,7019 13147,7019 13212,7019 13277,7019 12438,7046 12503,7046 12568,7046 10879,7078 13017,7084 13082,7084 13147,7084 13212,7084 13277,7084 13017,7149 13082,7149 13147,7149 13212,7149 13277,7149
  other v5: 13407.75,6875.56 13452.63,6875.56 13497.51,6875.56 13385.31,6901.15 13430.19,6901.15 13407.75,6926.74 13452.63,6926.74 13497.51,6926.74
HI_PWM: J5.63 J23.13 J24.13 J25.13 | length 8869.6
  Top Layer w10: J5.63@7760.35,7366.21 7760.35,7241.72 7847,7155.07 7847,6439.61 8113.14,6173.48 8150,6136.61 9291.34,6136.61 9378.6,6223.87 9549.99,6223.87 10365.24,5408.62 10365.24,5081.68 10342.93,5059.36 J25.13@10342.93,4915.43 J25.13@10342.93,4912.98
  Top Layer w20: v3(10342.93,738.93) J23.13@10342.93,803.3 ; v3(10342.93,2794.99) J24.13@10342.93,2859.36 ; v3@10342.93,4848.61 v3(10342.93,4851.06) J25.13@10342.93,4912.98
  Pwr Layer w10: v3(10342.93,738.93) 10342.93,811.07 10295,859 10295,2726 10342.93,2773.93 10342.93,4605.07 10295,4653 10295,4803.13 v3(10342.93,4851.06)
IGRID_A: L2.2 R5.1 R145.1 | length 345.2
  Top Layer w10: R145.1@2064.45,1151.5 2041.95,1174 2041.95,1326.95 2065,1350 R5.1@2192.83,1350
  other v1: 2286,1285 2286,1345 2286,1405
IGRID_B: L4.2 R41.1 R148.1 | length 345.2
  Top Layer w10: R148.1@2064.45,3701.5 2041.95,3724 2041.95,3876.95 2065,3900 R41.1@2192.83,3900
  other v1: 2286,3835 2286,3895 2286,3955
IGRID_C: L6.2 R47.1 R151.1 | length 345.2
  Top Layer w10: R151.1@2064.45,6201.5 2041.95,6224 2041.95,6376.95 2065,6400 R47.1@2192.83,6400
  other v1: 2286,6335 2286,6395 2286,6455
IIND_A: J17.2 J20.4 Q1.3 Q2.2 Q3.2 R168.1 U3.1 U3.2 U3.3 | length 1447.2
  Top Layer w30: J20.4@6369.7,572 v3(6369.7,638.93) ; R168.1@6895.35,800 6895.35,627.09 6950.44,572 J17.2@7133.48,572 v3(7133.48,638.93)
  Pwr Layer w30: Q2.2@6219.7,908.93 6219.7,774.24 6250,743.94 6346.06,743.94 6369.7,720.3 v3(6369.7,638.93)
  Bottom Layer w30: v3(7133.48,638.93) 7133.48,714.98 7162.44,743.94 7352.44,743.94 7398.48,789.98 Q1.3@7398.48,908.93
IIND_A_RTN: L1.2 U3.8 U3.9 U3.10
IIND_B: J9.4 J15.2 Q5.3 Q6.2 Q7.2 R169.1 U4.1 U4.2 U4.3 | length 1447.2
  Top Layer w30: J9.4@6369.7,2628.06 v3(6369.7,2694.99) ; R169.1@6895.35,2856.06 6895.35,2683.15 6950.44,2628.06 J15.2@7133.48,2628.06 v3(7133.48,2694.99)
  Pwr Layer w30: Q6.2@6219.7,2964.99 6219.7,2830.3 6250,2800 6346.06,2800 6369.7,2776.36 v3(6369.7,2694.99)
  Bottom Layer w30: v3(7133.48,2694.99) 7133.48,2771.04 7162.44,2800 7352.44,2800 7398.48,2846.04 Q5.3@7398.48,2964.99
IIND_B_RTN: L3.2 U4.8 U4.9 U4.10
IIND_C: J12.4 J16.2 Q9.3 Q10.2 Q11.2 R170.1 U6.1 U6.2 U6.3 | length 1447.2
  Top Layer w30: J12.4@6369.7,4684.13 v3(6369.7,4751.06) ; R170.1@6896.87,4909.76 6896.87,4736.84 6951.96,4681.76 J16.2@7135,4681.76 ; J16.2@7133.48,4684.13 v3(7133.48,4751.06)
  Pwr Layer w30: Q10.2@6219.7,5021.06 6219.7,4886.36 6250,4856.06 6346.06,4856.06 6369.7,4832.43 v3(6369.7,4751.06)
  Bottom Layer w30: v3(7133.48,4751.06) 7133.48,4827.1 7162.44,4856.06 7352.44,4856.06 7398.48,4902.1 Q9.3@7398.48,5021.06
IIND_C_RTN: L5.2 U6.8 U6.9 U6.10
ILA_FDBK: C41.2 J5.25 R28.2 | length 2671.5
  Top Layer w10: J5.25@7035.94,7366.21 7035.94,7240.06 v2(7189,7087) ; v2(9316,6897) C41.2@9316,6843.5 R28.2@9380,6843.5
  Bottom Layer w10: v2(7189,7087) 7242,7034 8616.24,7034 8760.11,6890.13 9309.13,6890.13 v2(9316,6897)
ILA_N: C77.2 R19.2 R26.1 U9.2 | length 10711.7
  Top Layer w10: U9.2@9199.7,6712.46 9199.7,6677.91 9184.7,6662.91 9184.7,6636.3 9197,6624 9292.2,6624 C77.2@9315.7,6647.5 9339.2,6624 9375.97,6624 ; R26.1@9380.7,6647.5 9378.4,6647.5 9378.7,6647.2 9375.97,6644.47 9375.97,6624 ; v2(9430.97,6636) 9418.97,6624 9375.97,6624
  Pwr Layer w10: v1(5700,5700) 6576.15,5700 6706.15,5570 6790.94,5570 6799.76,5578.81 6861.19,5578.81 6930,5510 6950.06,5510 v1(6980.06,5540)
  Bottom Layer w10: v1(5700,5700) 5264.72,5700 5084.14,5519.42 5084.14,2235.86 5220,2100 6590,2100 6665.35,2024.65 R19.2@6665.35,1952.56 ; v1(6980.06,5540) 6990,5549.94 6990,6110 7412.13,6532.13 8763.84,6532.13 8851.72,6620 9414.97,6620 v2(9430.97,6636)
ILA_P: R20.2 R30.2 U9.3 | length 10702.8
  Top Layer w10: U9.3@9149.7,6712.46 9149.7,6677.91 9164.7,6662.91 9164.7,6628.02 9188.72,6604 9292.2,6604 R30.2@9315.7,6580.5 9339.2,6604 9418.97,6604 v2(9430.97,6592)
  Pwr Layer w10: v1(5730,5670) 6580.87,5670 6700.87,5550 6799.23,5550 6808.04,5558.81 6852.9,5558.81 6921.72,5490 6970.9,5490 7019.94,5539.04 v1(7019.94,5540)
  Bottom Layer w10: v1(5730,5670) 5260,5670 5104.14,5514.14 5104.14,2244.14 5228.28,2120 6598.28,2120 6715.28,2003 R20.2@6715.28,1952.56 ; v1(7019.94,5540) 7010,5549.94 7010,6101.72 7420.41,6512.13 8772.13,6512.13 8860,6600 9422.97,6600 v2(9430.97,6592)
ILB_FDBK: C40.2 J5.37 R27.2 | length 2016.3
  Top Layer w10: J5.37@7224.92,7366.21 7224.92,7197.08 v2(7318,7104) ; v2(8820.7,6915) R27.2@8820.7,6845.5 C40.2@8885.7,6845.5
  Bottom Layer w10: v2(7318,7104) 7370,7052 8621,7052 8621.13,7051.87 8623.64,7051.87 8760.52,6915 v2(8820.7,6915)
ILB_N: C79.2 R21.2 R25.1 U9.6 | length 7984
  Top Layer w10: v2(8770.43,6631) 8782.43,6619 8825.43,6619 ; R25.1@8820.7,6642.5 8823,6642.5 8822.7,6642.2 8825.43,6639.47 8825.43,6619 ; C79.2@8883.7,6647.5 C79.2@8887.2,6644 ; U9.6@8999.7,6712.46 8999.7,6677.91 9014.7,6662.91 9014.7,6636.3 8997.4,6619 8909.2,6619 C79.2@8885.7,6642.5 8862.2,6619 8825.43,6619
  Pwr Layer w10: v1(5730,5630) 6590,5630 6700,5520 6810.06,5520 v1(6820,5529.94)
  Bottom Layer w10: v1(5730,5630) 5248.28,5630 5122.02,5503.73 5122.02,4257.98 5265,4115 6625,4115 6670,4070 R21.2@6670,4011.5 ; v1(6820,5529.94) 6829.94,5520 6878.15,5520 6950,5591.85 6950,6358.28 7161.72,6570 8695,6570 8744,6619 8758.43,6619 v2(8770.43,6631)
ILB_P: R22.2 R29.2 U9.5 | length 7957.9
  Top Layer w10: v2(8770.43,6587) 8782.43,6599 8862.2,6599 R29.2@8885.7,6575.5 8909.2,6599 9005.69,6599 9034.7,6628.02 9034.7,6662.91 9049.7,6677.91 U9.5@9049.7,6712.46
  Pwr Layer w10: v1(5700,5600) 6594.72,5600 6694.72,5500 6810.06,5500 v1(6820,5490.06)
  Bottom Layer w10: v1(5700,5600) 5243.56,5600 5142.02,5498.45 5142.02,4266.27 5273.28,4135 6633.28,4135 6719.93,4048.35 6719.93,4018.15 R22.2@6719.93,4011.5 ; v1(6820,5490.06) 6829.94,5500 6886.44,5500 6970,5583.56 6970,6350 7170,6550 8703.28,6550 8752.28,6599 8758.43,6599 v2(8770.43,6587)
ILC_FDBK: C45.2 J5.34 R40.2 | length 3205.5
  Top Layer w10: v2(7040,7674) 7138,7674 7161.92,7650.07 J5.34@7161.93,7500.07 ; v2(8715,6828) 8715,6559 8791,6483 C45.2@8791,6367.76 R40.2@8856,6367.76
  Bottom Layer w10: v2(7040,7674) 7040,7091 7136.87,6994.13 8548.87,6994.13 v2(8715,6828)
ILC_N: C81.2 R23.2 R31.1 U9.9 | length 2697.5
  Top Layer w10: R23.2@7011.5,5810 7061.72,5810 7106,5854.28 v2(7106,5954) ; R31.1@8992.5,6303.57 R31.1@8992.8,6303.27 8995.53,6306 9016,6306 ; U9.9@8999.7,6497.89 8999.7,6463.35 9014.7,6448.35 9014.7,6388.47 C81.2@8992.5,6366.27 9016,6342.76 9016,6306 ; v2(9004,6251) 9016,6263 9016,6306
  Bottom Layer w10: v2(7106,5954) 7094,5966 7094,5983.72 7458.28,6348 8971,6348 9016,6303 9016,6263 v2(9004,6251)
ILC_P: R24.2 R33.2 U9.10 | length 2654
  Top Layer w10: R24.2@7011.5,5870 7048.18,5870 7062,5883.82 v2(7062,5954) ; v2(9048,6251) 9036,6263 9036,6342.76 R33.2@9059.5,6366.27 9034.7,6391.07 9034.7,6448.35 9049.7,6463.35 U9.10@9049.7,6497.89
  Bottom Layer w10: v2(7062,5954) 7074,5966 7074,5992 7450,6368 8979.28,6368 9036,6311.28 9036,6263 v2(9048,6251)
LI_PWM: J5.61 J23.11 J24.11 J25.11 | length 8906.8
  Top Layer w10: J5.61@7728.85,7366.21 7728.85,7247.93 7829.13,7147.66 7829.13,6432.21 8105.73,6155.6 8142.6,6118.74 9298.74,6118.74 9386,6206 9542.59,6206 10347.37,5401.22 10347.37,5089.08 10242.93,4984.64 J25.11@10242.93,4915.43
  Top Layer w20: v3(10242.93,738.93) J23.11@10242.93,803.3 ; v3(10242.93,2794.99) J24.11@10242.93,2859.36 ; v3(10242.93,4851.06) J25.11@10242.93,4915.43
  Pwr Layer w10: v3(10242.93,738.93) 10197,784.86 10197,2749.06 v3(10242.93,2794.99) 10242.93,4605.07 10193,4655 10193,4801.13 v3(10242.93,4851.06)
NetC8_2: C8.2 R16.2
NetC9_2: C9.2 R17.2
NetC10_2: C10.2 R18.2
NetC14_2: C14.2 C15.1 L7.2 U8.8
NetC16_2: C16.2 C26.2 C33.2 R53.1 R90.1 T1.2 U2.2 | length 693.3
  Top Layer w20: T1.2@3538.64,421 3563,421 3588.99,446.99 C33.2@3633,446.99 3658.09,472.09 C16.2@3734,472.09 3760.91,472.09 3808,425 3864.87,425 3904,425 ; R90.1@3928.5,326 3919,335.5 3919,410 3904,425 ; R53.1@3928.5,593 C26.2@3928.5,531 3919.01,521.51 3919.01,440.01 3904,425
NetC17_2: C17.2 C27.2 C34.2 R63.1 R154.1 T2.2 U7.2 | length 693.3
  Top Layer w20: T2.2@3538.64,2971 3563,2971 3588.99,2996.99 C34.2@3633,2996.99 3658.09,3022.09 C17.2@3734,3022.09 3760.91,3022.09 3808,2975 3864.87,2975 3904,2975 ; R154.1@3928.5,2876 3919,2885.5 3919,2960 3904,2975 ; R63.1@3928.5,3143 C27.2@3928.5,3081 3919.01,3071.51 3919.01,2990.01 3904,2975
NetC19_1: C19.1 L16.1 U11.1 U11.2 U11.3 U11.4 U11.5 | length 76.7
  Top Layer w10: C19.1@13422.38,6757 13432.94,6767.57 U11.5@13432.94,6829.3
NetC19_2: C19.2 U11.6 | length 79.3
  Top Layer w10: U11.6@13452.63,6829.3 13452.63,6795 13469.62,6778.01 C19.2@13469.62,6757
NetC20_1: C20.1 C21.2 L8.2 U1.8
NetC22_1: C22.1 C23.1 L9.2 U3.14
NetC24_1: C24.1 C25.1 L10.2 U4.14
NetC29_2: C29.2 C30.1 L13.2 U5.8
NetC31_1: C31.1 C32.1 L14.2 U6.14
NetC38_1: C38.1 U11.8 | length 206.7
  Top Layer w10: U11.8@13492,6829.3 13492,6790 13507,6775 13507,6754
  Top Layer w15: 13507,6754 13507,6725 C38.1@13575,6657
NetC46_2: C46.2 J5.76 R37.2 | length 254.1
  Top Layer w10: C46.2@7865.63,7672.5 7869.13,7669 7949.33,7669 J5.76@7949.33,7500.07
NetC61_1: C61.1 C64.1 L19.2 U12.1
NetC69_2: C69.2 R139.2 R141.1 U19.12 | length 250.7
  Top Layer w10: R139.2@8186.2,6938 R141.1@8186.2,6873 C69.2@8186.2,6808 8186.2,6805.8 8246.83,6745.17 U19.12@8246.83,6712.46
NetC71_2: C71.2 R142.2 R144.1 U20.3 | length 204.8
  Top Layer w20: R142.2@6390,6595 6390.67,6594.33 R144.1@6458.5,6594.33 C71.2@6458.5,6533 6472.6,6518.91 U20.3@6472.6,6464.13
NetC77_1: C77.1 R26.2 R28.1 U9.1 | length 202.1
  Top Layer w10: U9.1@9249.7,6712.46 9313.74,6712.46 C77.1@9315.7,6710.5 R26.2@9380.7,6710.5 9380.7,6779.8 R28.1@9380,6780.5
NetC78_1: C78.1 D12.2 D13.1 R145.2 U1.2 | length 499.6
  Top Layer w10: U1.2@2059.45,894.57 2059.45,988.5 C78.1@2065.94,995 R145.2@2065.94,1087.01 ; R145.2@2064.45,1088.5 R145.2@2065.94,1087.01 ; v2(2104.4,1090.51) 2069.45,1090.51 R145.2@2065.94,1087.01
  Top Layer w12: D13.1@1915.24,1014.6 1956.39,1014.6 v2(1956.9,1015.1)
  Bottom Layer w12: D12.2@1915.24,1014.6 2028.49,1014.6 v2(2104.4,1090.51)
NetC78_2: C78.2 D12.1 D13.2 R147.2 U1.3 | length 332.3
  Top Layer w10: v2(1964.5,1088.5) R147.2@1999.45,1088.5 2002.95,1085 C78.2@2002.95,995 2009.45,988.5 U1.3@2009.45,894.57
  Top Layer w12: D13.2@1915.24,1089.4 1963.6,1089.4 v2(1964.5,1088.5)
  Bottom Layer w12: D12.1@1915.24,1089.4 1963.6,1089.4 v2(1964.5,1088.5)
NetC79_1: C79.1 R25.2 R27.1 U9.7 | length 208.9
  Top Layer w10: R27.1@8820.7,6782.5 R25.2@8820.7,6705.5 C79.1@8885.7,6705.5 8892.66,6712.46 U9.7@8949.7,6712.46
NetC80_1: C80.1 D14.2 D15.1 R148.2 U5.2 | length 499.6
  Top Layer w10: U5.2@2059.45,3444.57 2059.45,3538.5 C80.1@2065.94,3545 R148.2@2065.94,3637.01 ; R148.2@2064.45,3638.5 R148.2@2065.94,3637.01 ; v2(2104.4,3640.51) 2069.45,3640.51 R148.2@2065.94,3637.01
  Top Layer w12: D15.1@1915.24,3564.6 1956.39,3564.6 v2(1956.9,3565.1)
  Bottom Layer w12: D14.2@1915.24,3564.6 2028.49,3564.6 v2(2104.4,3640.51)
NetC80_2: C80.2 D14.1 D15.2 R150.2 U5.3 | length 332.3
  Top Layer w10: v2(1964.5,3638.5) R150.2@1999.45,3638.5 2002.95,3635 C80.2@2002.95,3545 2009.45,3538.5 U5.3@2009.45,3444.57
  Top Layer w12: D15.2@1915.24,3639.4 1963.6,3639.4 v2(1964.5,3638.5)
  Bottom Layer w12: D14.1@1915.24,3639.4 1963.6,3639.4 v2(1964.5,3638.5)
NetC81_1: C81.1 R31.2 R40.1 U9.8 | length 277.5
  Top Layer w10: R40.1@8856,6304.77 8857.5,6303.27 R31.2@8929.8,6303.27 8929.5,6303.57 C81.1@8929.5,6366.27
  Top Layer w12: C81.1@8929.5,6366.27 8929.5,6407.5 8949.7,6427.7 U9.8@8949.7,6497.89
NetC82_1: C82.1 D16.2 D17.1 R151.2 U8.2 | length 499.6
  Top Layer w10: U8.2@2059.45,5944.57 2059.45,6038.5 C82.1@2065.94,6045 R151.2@2065.94,6137.01 ; R151.2@2064.45,6138.5 R151.2@2065.94,6137.01 ; v2(2104.4,6140.51) 2069.45,6140.51 R151.2@2065.94,6137.01
  Top Layer w12: D17.1@1915.24,6064.6 1956.39,6064.6 v2(1956.9,6065.1)
  Bottom Layer w12: D16.2@1915.24,6064.6 2028.49,6064.6 v2(2104.4,6140.51)
NetC82_2: C82.2 D16.1 D17.2 R153.2 U8.3 | length 332.3
  Top Layer w10: v2(1964.5,6138.5) R153.2@1999.45,6138.5 2002.95,6135 C82.2@2002.95,6045 2009.45,6038.5 U8.3@2009.45,5944.57
  Top Layer w12: D17.2@1915.24,6139.4 1963.6,6139.4 v2(1964.5,6138.5)
  Bottom Layer w12: D16.1@1915.24,6139.4 1963.6,6139.4 v2(1964.5,6138.5)
NetC83_1: C83.1 R39.1 R46.1 U18.1 | length 255
  Top Layer w10: R46.1@6860.11,6334.5 6860.61,6335 R39.1@6933.41,6335 6945.41,6347 6945.41,6405.24 C83.1@6953.17,6413 6966.24,6426.08 U18.1@6966.24,6502.89
NetC84_1: C84.1 R94.1 R99.1 U19.1 | length 267.4
  Top Layer w10: R99.1@8038.7,6304.5 8088.5,6304.5 R94.1@8114,6330 8126,6342 8126,6400.24 C84.1@8133.76,6408 8146.83,6421.08 U19.1@8146.83,6497.89
NetC85_1: C85.1 R61.1 R71.1 U18.7 | length 276.7
  Top Layer w10: U18.7@7266.24,6502.89 7266.24,6484.17 7336.91,6413.5 C85.1@7336.91,6413 7336.91,6353.5 7355.91,6334.5 R71.1@7427.11,6334.5
NetC86_1: C86.1 R105.1 R111.1 U19.7 | length 276.7
  Top Layer w10: U19.7@8446.83,6497.89 8446.83,6479.17 8517.5,6408.5 C86.1@8517.5,6408 8517.5,6348.5 R105.1@8536,6330 8536.5,6329.5 R111.1@8607.7,6329.5
NetC87_1: C87.1 R79.1 R84.1 U18.8 | length 313.6
  Top Layer w10: U18.8@7266.24,6717.46 7266.24,6786.34 7293.91,6814 C87.1@7290.91,6814 7303.41,6826.5 7303.41,6886 R79.1@7312.41,6895 7312.41,6882.09 R84.1@7383,6811.5
NetC88_1: C88.1 R117.1 R122.1 U19.8 | length 299.8
  Top Layer w10: U19.8@8446.83,6712.46 8446.83,6781.34 8474.5,6809 C88.1@8471.5,6809 8484,6821.5 8484,6881 R117.1@8493,6890 8493,6883 8534.5,6841.5 R122.1@8567.7,6841.5
NetC101_2: C101.2 C103.1 L11.2 R155.1
NetC102_2: C102.2 C104.1 L12.2 R157.1
NetC105_2: C105.2 L11.1 U10.3 | length 141.9
  Top Layer w20: 2649.09,427.4 U10.3@2669.13,427.4 2688.4,427.4 2744,483 2744,507
NetC106_2: C106.2 L12.1 U21.3 | length 141.9
  Top Layer w20: 2649.09,2977.4 U21.3@2669.13,2977.4 2688.4,2977.4 2744,3033 2744,3057
NetC107_2: C107.2 C108.2 C109.2 R159.1 R160.1 T3.2 U22.2 | length 693.3
  Top Layer w20: T3.2@3538.64,5471 3563,5471 3588.99,5496.99 C109.2@3633,5496.99 3658.09,5522.09 C107.2@3734,5522.09 3760.91,5522.09 3808,5475 3864.87,5475 3904,5475 ; R160.1@3928.5,5376 3919,5385.5 3919,5460 3904,5475 ; R159.1@3928.5,5643 C108.2@3928.5,5581 3919.01,5571.51 3919.01,5490.01 3904,5475
NetC114_2: C114.2 C115.1 L15.2 R161.1
NetC116_2: C116.2 L15.1 U23.3 | length 141.9
  Top Layer w20: 2649.09,5477.4 U23.3@2669.13,5477.4 2688.4,5477.4 2744,5533 2744,5557
NetC132_2: C132.2 R128.2 R130.1 U9.12 | length 274.9
  Top Layer w20: U9.12@9149.7,6497.89 9149.7,6443.99 9186.9,6406.8 C132.2@9186.9,6365.24 R130.1@9250.46,6365.24 R128.2@9313.74,6365.24
NetC133_1: C133.1 R131.1 R136.1 U18.14 | length 322.4
  Top Layer w10: R136.1@6801.5,6813.43 6801.5,6816.5 R131.1@6880,6895 ; R131.1@6880,6890 6900,6870 6900,6818.5 6966.24,6752.26 U18.14@6966.24,6717.46
NetD1_1: D1.1 D3.1 | length 109.3
  Top Layer w80: D3.1@1106.74,3102 D1.1@1216,3102
NetD2_1: D2.1 D6.1 | length 109.3
  Top Layer w80: D6.1@1106.74,5049 D2.1@1216,5049
NetD3_2: D3.2 K1.4 Q15.2 Q15.4 | length 817.3
  Top Layer w40: 731,3232 Q15.2@731,3331.17
  Top Layer w80: 731,3232 Q15.4@731,3102.83 731.83,3102 D3.2@949.26,3102 949.26,2732.74 K1.4@950,2732
NetD4_1: D4.1 D7.1 | length 109.3
  Top Layer w80: D7.1@1106.74,7265 D4.1@1216,7265
NetD5_1: D5.1 D8.1 | length 109.3
  Top Layer w80: D8.1@1106.74,1480 D5.1@1216,1480
NetD6_2: D6.2 K2.4 Q16.2 Q16.4 | length 815.9
  Top Layer w40: 731,5179 Q16.2@731,5277.17
  Top Layer w80: 731,5179 Q16.4@731,5048.83 731.17,5049 D6.2@949.26,5049 K2.4@949.26,4679.74
NetD7_2: D7.2 K3.4 Q17.2 Q17.4 | length 817.3
  Top Layer w40: 731,7399 Q17.2@731,7494.17
  Top Layer w80: 731,7399 Q17.4@731,7265.83 731.83,7265 D7.2@949.26,7265 949.26,6895.74 K3.4@950,6895
NetD8_2: D8.2 K4.4 Q18.2 Q18.4 | length 913.9
  Top Layer w40: 661,1547 Q18.2@661,1643.17
  Top Layer w80: 661,1547 Q18.4@661,1414.83 775.83,1414.83 841,1480 D8.2@949.26,1480 949.26,1110.74 K4.4@950,1110
NetD9_2: D9.2 T1.6 | length 114.6
  Top Layer w40: D9.2@2989.47,275 3052,275 3077.92,300.92 T1.6@3093.36,300.92
NetD11_2: D11.2 T2.6 | length 114.6
  Top Layer w40: D11.2@2989.47,2825 3052,2825 3077.92,2850.92 T2.6@3093.36,2850.92
NetD18_2: D18.2 R207.1 | length 61
  Top Layer w30: D18.2@11431.5,6624.02 R207.1@11431.5,6685
NetD19_2: D19.2 R208.1 | length 64
  Top Layer w25: D19.2@10224,6847.48 R208.1@10224,6911.5
NetD24_2: D24.2 T1.4 | length 113.3
  Top Layer w40: D24.2@2990,565 3052,565 3075.92,541.08 T1.4@3093.36,541.08
NetD25_2: D25.2 T2.4 | length 113.3
  Top Layer w40: D25.2@2990,3115 3052,3115 3075.92,3091.08 T2.4@3093.36,3091.08
NetD26_2: D26.2 R156.1 | length 64.7
  Top Layer w20: D26.2@2385,678.82 R156.1@2385,743.5
NetD27_2: D27.2 R158.1 | length 64.7
  Top Layer w20: D27.2@2385,3228.82 R158.1@2385,3293.5
NetD30_2: D30.2 T3.6 | length 114.6
  Top Layer w40: D30.2@2989.47,5325 3052,5325 3077.92,5350.92 T3.6@3093.36,5350.92
NetD31_2: D31.2 T3.4 | length 113.3
  Top Layer w40: D31.2@2990,5615 3052,5615 3075.92,5591.08 T3.4@3093.36,5591.08
NetD32_2: D32.2 R162.1 | length 64.7
  Top Layer w20: D32.2@2385,5728.82 R162.1@2385,5793.5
